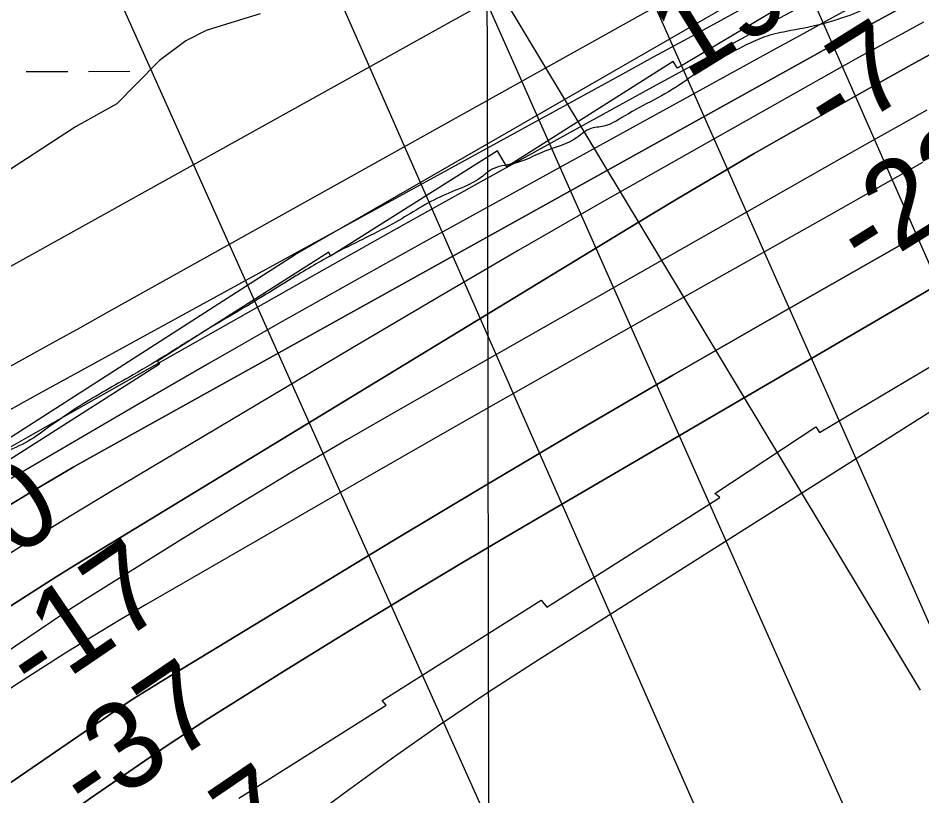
# Model space of a CAD drawing. Extents: x 3324104 to 3361979, y 612876 to 638273.
# Drawn here: x 3354171 to 3354870, y 621658 to 622260 of the extents above; entities that cross this region are included whole.
import ezdxf

# ---------------------------------------------------------------- set-up
doc = ezdxf.new("R2010")
doc.units = 0
for name, color, linetype in [('V-GRID-MAJR', 7, 'Continuous'), ('V-RIVR-EDGE', 7, 'Continuous'), ('V-RIVR-RANG', 7, 'Continuous'), ('V-RRAP-FSHR', 7, 'Continuous'), ('V-RRAP-RVMT', 7, 'Continuous'), ('V-TOPO-DPTH', 7, 'Continuous'), ('V-TOPO-MAJR', 7, 'Continuous'), ('V-TOPO-MINR', 7, 'Continuous'), ('V-TOPO-WATR', 7, 'Continuous'), ('V-UTIL-LINE', 7, 'Continuous'), ('V-WETL-SWMP', 7, 'Continuous')]:
    doc.layers.add(name, color=color, linetype=linetype)

msp = doc.modelspace()

# ---------------------------------------------------------------- linework, layer by layer
at = {"layer": 'V-GRID-MAJR'}
msp.add_spline([(3354542.62, 618302.88), (3354530.28, 624362.21), (3354517.94, 630423.47), (3354505.59, 636484.76), (3354505.59, 636486.67)], degree=3, dxfattribs=at)
at = {"layer": 'V-RIVR-EDGE'}
msp.add_spline([(3356051.95, 622889.63), (3356029.15, 622881.43), (3356012.46, 622875.66), (3355994.6, 622867.17), (3355977.52, 622859.07), (3355958.5, 622850.97), (3355948.4, 622843.24), (3355934.03, 622834.75), (3355904.12, 622817.76), (3355878.1, 622802.31), (3355856.74, 622790.34), (3355829.95, 622776.44), (3355805.11, 622765.65), (3355764.72, 622744.81), (3355744.14, 622733.61), (3355694.06, 622710.85), (3355668.43, 622698.12), (3355641.64, 622685), (3355605.15, 622669.19), (3355569.44, 622657.26), (3355539.17, 622646.47), (3355510.83, 622636.85), (3355482.11, 622628.39), (3355461.93, 622623.01), (3355442.52, 622614.14), (3355422.73, 622607.21), (3355409.53, 622603.36), (3355388.97, 622597.59), (3355371.88, 622589.49), (3355348.98, 622581.02), (3355297.71, 622547.02), (3355260.04, 622525.78), (3355211.1, 622494.49), (3355190.13, 622484.46), (3355184.7, 622482.92), (3355179.26, 622477.89), (3355174.21, 622475.58), (3355160.62, 622470.96), (3355143.54, 622463.63), (3355133.06, 622457.07), (3355125.67, 622450.49), (3355113.25, 622443.93), (3355096.93, 622433.11), (3355081.02, 622426.95), (3355064.32, 622419.23), (3355056.95, 622418.86), (3355048.8, 622414.62), (3355041.8, 622406.88), (3355036.76, 622406.5), (3355031.32, 622405.74), (3355027.05, 622404.2), (3355017.34, 622396.08), (3355010.74, 622394.93), (3355001.42, 622388.36), (3354988.6, 622379.09), (3354972.29, 622369.43), (3354947.44, 622356.31), (3354937.73, 622351.68), (3354926.08, 622343.56), (3354903.15, 622326.56), (3354891.11, 622318.06), (3354883.33, 622307.22), (3354879.44, 622304.12), (3354875.17, 622302.58), (3354867.8, 622299.11), (3354853.03, 622288.29), (3354842.54, 622279.01), (3354826.61, 622267.41), (3354807.2, 622259.71), (3354793.23, 622255.47), (3354765.68, 622249.73), (3354748.61, 622245.5), (3354734.63, 622239.33), (3354712.11, 622227.37), (3354697.74, 622218.87), (3354685.31, 622209.98), (3354640.65, 622184.5), (3354622.01, 622176.01), (3354616.19, 622175.25), (3354603.38, 622167.52), (3354578.92, 622157.11), (3354554.46, 622147.48), (3354537.39, 622142.87), (3354530.78, 622137.84), (3354500.11, 622122.79), (3354463.61, 622102.33), (3354417.79, 622078.79), (3354386.33, 622060.64), (3354340.11, 622032.44), (3354321.08, 622021.25), (3354284.96, 621998.84), (3354257, 621982.24), (3354217, 621958.68), (3354194.08, 621942.84), (3354176.99, 621931.63), (3354157.57, 621921.98), (3354141.64, 621910.39), (3354135.42, 621904.2), (3354130.36, 621897.62), (3354120.65, 621891.05), (3354103.96, 621882.95), (3354075.58, 621856.65), (3354044.89, 621835.39), (3354013.04, 621812.21), (3353971.47, 621781.67), (3353947.77, 621763.5), (3353941.17, 621763.52), (3353935.35, 621762.76), (3353929.53, 621760.06), (3353924.87, 621756.58), (3353920.59, 621751.55), (3353917.08, 621742.64), (3353910.48, 621741.49), (3353904.66, 621738.4), (3353893.78, 621731.06), (3353879.8, 621721.4), (3353866.19, 621708.64), (3353854.92, 621697.42), (3353843.26, 621687.75), (3353839.77, 621688.54), (3353831.23, 621686.23), (3353823.08, 621681.21), (3353818.03, 621677.34), (3353800.94, 621666.14), (3353790.85, 621663.06), (3353781.91, 621654.94), (3353777.63, 621651.85), (3353776.07, 621648.75), (3353775.67, 621643.71), (3353772.18, 621641), (3353755.87, 621632.13), (3353735.68, 621622.09), (3353718.58, 621608.17), (3353704.21, 621600.45), (3353694.12, 621596.6), (3353683.64, 621592.36), (3353671.21, 621584.25), (3353642.07, 621562.99), (3353598.95, 621534.01), (3353578.37, 621522.43), (3353556.23, 621507.75), (3353547.68, 621501.95), (3353525.93, 621489.21), (3353513.12, 621481.09), (3353497.18, 621468.34), (3353476.98, 621450.94), (3353453.28, 621436.65), (3353435.8, 621424.67), (3353404.72, 621401.09), (3353378.3, 621380.21), (3353361.59, 621368.62), (3353339.46, 621355.1), (3353319.65, 621342.35), (3353299.45, 621329.99), (3353283.54, 621324.6), (3353273.05, 621317.65), (3353254.77, 621295.98), (3353236.88, 621275.47), (3353219.39, 621258.83), (3353195.69, 621241.44), (3353168.49, 621221.34), (3353137.81, 621201.64), (3353112.17, 621185.03), (3353065.55, 621151.79), (3353022.05, 621122.82), (3352993.29, 621100.39), (3352956, 621073.34), (3352907.05, 621037.78), (3352853.8, 620991.77), (3352787.76, 620942.29), (3352749.68, 620913.3), (3352736.85, 620900.92), (3352733.34, 620892.79), (3352728.67, 620886.59), (3352718.96, 620881.19), (3352691.78, 620864.58), (3352660.31, 620841.78), (3352640.5, 620828.25), (3352623.39, 620811.23), (3352605.12, 620792.27), (3352593.46, 620783), (3352582.59, 620778.76), (3352566.29, 620771.43), (3352548.04, 620764.49), (3352522.41, 620750.98), (3352494.45, 620735.54), (3352482.41, 620727.04), (3352479.3, 620723.17), (3352476.96, 620717.36), (3352470.74, 620711.94), (3352455.99, 620707.33), (3352443.18, 620700.38), (3352419.1, 620685.7), (3352392.3, 620669.09), (3352362.78, 620650.94), (3352339.08, 620634.32), (3352315.38, 620615.38), (3352284.68, 620590.63), (3352258.65, 620571.31), (3352228.74, 620550.05), (3352193.39, 620527.65), (3352156.88, 620504.86), (3352131.63, 620487.47), (3352093.95, 620462.36), (3352049.28, 620432.99), (3351990.23, 620391.26), (3351936.63, 620357.26), (3351851.55, 620293.87), (3351833.29, 620281.51), (3351816.98, 620273.79), (3351794.06, 620257.95), (3351767.65, 620240.95), (3351719.86, 620206.17), (3351680.63, 620177.57), (3351657.32, 620160.56), (3351637.11, 620145.87), (3351623.13, 620135.44), (3351603.32, 620124.24), (3351588.57, 620120.01), (3351567.22, 620109.59), (3351552.08, 620103.43), (3351538.1, 620096.48), (3351523.73, 620086.43), (3351510.91, 620076.38), (3351503.52, 620069.81), (3351495.35, 620057.42), (3351486, 620042.32), (3351479.39, 620032.64), (3351469.67, 620022.58), (3351448.3, 620006.34), (3351431.59, 619994.75), (3351404.78, 619973.88), (3351377.97, 619951.84), (3351358.93, 619936.37), (3351332.12, 619915.5), (3351306.08, 619892.29), (3351274.58, 619858.25), (3351238.83, 619826.92), (3351215.12, 619805.65), (3351171.59, 619767.75), (3351145.54, 619739.51), (3351124.55, 619722.11), (3351105.9, 619707.81), (3351089.59, 619696.99), (3351079.49, 619691.2), (3351074.04, 619683.45), (3351058.1, 619666.43), (3351043.34, 619655.22), (3351015.36, 619633.96), (3350999.05, 619623.14), (3350992.05, 619617.34), (3350979.23, 619606.13), (3350966.01, 619594.53), (3350951.25, 619582.15), (3350935.7, 619567.84), (3350923.26, 619555.08), (3350910.05, 619544.25), (3350888.29, 619528.02), (3350846.74, 619504.08), (3350821.49, 619490.18), (3350811.39, 619483.61), (3350805.96, 619480.52), (3350800.9, 619473.16), (3350797.41, 619473.17), (3350793.92, 619474.35), (3350788.88, 619473.58), (3350786.93, 619472.04), (3350785.37, 619467.39), (3350785.36, 619462.73), (3350779.53, 619456.15), (3350765.93, 619445.72), (3350746.11, 619428.7), (3350722.4, 619408.98), (3350716.19, 619407.06), (3350713.08, 619403.96), (3350711.13, 619396.99), (3350708.79, 619391.57), (3350704.52, 619391.58), (3350693.26, 619385.79), (3350686.65, 619379.6), (3350679.64, 619368.37), (3350661.38, 619354.45), (3350648.56, 619344.4), (3350645.46, 619344.8), (3350638.47, 619339.39), (3350623.32, 619330.5), (3350616.33, 619326.26), (3350602.35, 619317.37), (3350598.83, 619308.85), (3350582.91, 619299.19), (3350553.77, 619276), (3350526.18, 619255.51), (3350493.55, 619231.94), (3350474.9, 619219.57), (3350474.5, 619213.76), (3350470.22, 619207.17), (3350458.96, 619202.55), (3350446.14, 619194.05), (3350441.09, 619189.79), (3350438.76, 619186.31), (3350434.48, 619180.89), (3350414.67, 619167.76), (3350401.46, 619159.26), (3350384.75, 619146.89), (3350369.6, 619133.74), (3350356.39, 619125.24), (3350350.95, 619119.05), (3350347.43, 619109.36), (3350338.1, 619097.75), (3350324.88, 619083.82), (3350308.55, 619069.9), (3350300.39, 619062.56), (3350296.13, 619062.57), (3350291.47, 619062.19), (3350274.77, 619050.6), (3350258.45, 619037.45), (3350251.84, 619032.81), (3350244.08, 619029.34), (3350233.61, 619028.21), (3350227.39, 619024.34), (3350220.39, 619016.99), (3350213, 619007.32), (3350202.12, 618996.87), (3350193.57, 618989.52), (3350179.6, 618985.29), (3350173.77, 618980.65), (3350164.84, 618977.96), (3350162.12, 618975.25), (3350159.39, 618971.38), (3350154.33, 618963.64), (3350145.78, 618953.19), (3350125.96, 618938.11), (3350102.66, 618923.05), (3350094.5, 618918.41), (3350086.34, 618913), (3350075.07, 618901.01), (3350064.19, 618892.12), (3350039.32, 618873.57), (3350021.84, 618861.59), (3350002.03, 618848.84), (3349991.94, 618844.21), (3349964.36, 618826.44), (3349938.72, 618807.11), (3349915.41, 618792.82), (3349892.5, 618778.92), (3349868.02, 618761.91), (3349852.49, 618753.03), (3349842.79, 618749.95), (3349830.35, 618739.13), (3349804.32, 618720.19), (3349777.9, 618697.76), (3349751.86, 618677.66), (3349729.72, 618661.43), (3349703.69, 618642.88), (3349678.84, 618629.75), (3349648.93, 618611.99), (3349624.46, 618594.99), (3349592.61, 618575.67), (3349570.48, 618564.87), (3349549.5, 618548.63), (3349505.21, 618518.11), (3349479.19, 618499.94), (3349471.42, 618494.53), (3349458.99, 618487.59), (3349438.4, 618472.12), (3349412.37, 618452.41), (3349379.73, 618429.61), (3349350.21, 618410.29), (3349303.2, 618374.73), (3349277.56, 618357.73), (3349263.97, 618347.29), (3349241.43, 618330.68), (3349226.67, 618319.85), (3349207.25, 618306.33), (3349193.17, 618293.54)], degree=3, dxfattribs=at)
at = {"layer": 'V-RIVR-RANG'}
msp.add_line((3354405.13, 622511.41), (3354869.13, 621740.23), dxfattribs=at)
at = {"layer": 'V-RRAP-FSHR'}
msp.add_lwpolyline([(3353211.76, 621284.79), (3354078.79, 621880.27), (3354385.88, 622077.34), (3354728.27, 622274.75), (3355278, 622569.49)], dxfattribs=at)
at = {"layer": 'V-RRAP-RVMT'}
for p, q in [((3354756.89, 622266.36), (3354681.44, 622221.28)), ((3354678.17, 622226.64), (3354549.53, 622145.06)), ((3354681.44, 622221.28), (3354678.17, 622226.64)), ((3354542.13, 622157.35), (3354413.04, 622075.9)), ((3354549.53, 622145.06), (3354542.13, 622157.35)), ((3354411.89, 622078.93), (3354279.26, 621994.82)), ((3354413.04, 622075.9), (3354411.89, 622078.93)), ((3354791.24, 621939.49), (3354900.92, 622004.91)), ((3354279.26, 621994.82), (3354280.77, 621992.32)), ((3354280.77, 621992.32), (3354052.63, 621846.84)), ((3354710.25, 621892.46), (3354788.5, 621944.06)), ((3354788.5, 621944.06), (3354791.24, 621939.49)), ((3354714.16, 621889.31), (3354710.25, 621892.46)), ((3354580.26, 621804.39), (3354714.16, 621889.31)), ((3354453.14, 621732.22), (3354576.1, 621809.95)), ((3354576.1, 621809.95), (3354580.26, 621804.39)), ((3354456.23, 621728.65), (3354453.14, 621732.22)), ((3354342.29, 621656.79), (3354456.23, 621728.65))]:
    msp.add_line(p, q, dxfattribs=at)
at = {"layer": 'V-TOPO-DPTH'}
for points in [[(3355320.3, 622563.61), (3354850.48, 622309.01), (3354820.61, 622292.81), (3354790.74, 622276.59), (3354760.88, 622260.36), (3354731.03, 622244.11), (3354662.2, 622206.62), (3354598.02, 622171.46), (3354533.96, 622136.1), (3354470.07, 622100.43), (3354406.29, 622064.56), (3354179.12, 621936.06), (3354160.95, 621925.62), (3354142.87, 621915), (3354124.95, 621904.12), (3354107.13, 621893.08), (3354004.93, 621828.76), (3353936.34, 621785.05), (3353868.06, 621740.85), (3353800.28, 621695.89)], [(3353707.63, 621578.6), (3354161.88, 621881.5), (3354164.42, 621883.15), (3354166.99, 621884.74), (3354184.37, 621895.24), (3354194.38, 621901.21), (3354204.44, 621907.12), (3354214.56, 621912.91), (3354224.73, 621918.63), (3354783.66, 622229.28), (3354796.78, 622236.56), (3354809.92, 622243.81), (3354823.08, 622251.02), (3354836.25, 622258.22), (3354942.17, 622315.88)], [(3353707.63, 621578.6), (3354161.88, 621881.5), (3354164.42, 621883.15), (3354166.99, 621884.74), (3354184.37, 621895.24), (3354194.38, 621901.21), (3354204.44, 621907.12), (3354214.56, 621912.91), (3354224.73, 621918.63), (3354783.66, 622229.28), (3354796.78, 622236.56), (3354809.92, 622243.81), (3354823.08, 622251.02), (3354836.25, 622258.22), (3354942.17, 622315.88)], [(3353803.01, 621568.04), (3353882.11, 621620.39), (3353961.41, 621672.42), (3354040.85, 621724.25), (3354168.82, 621807.38), (3354184.42, 621817.42), (3354200.08, 621827.36), (3354215.83, 621837.16), (3354231.63, 621846.87), (3354650.52, 622101.65), (3354680.51, 622119.72), (3354710.59, 622137.62), (3354740.82, 622155.27), (3354771.15, 622172.75), (3354801.61, 622190.02), (3354832.12, 622207.18), (3354862.73, 622224.17), (3354893.41, 622241.04)], [(3354893.41, 622241.04), (3354862.73, 622224.17), (3354832.12, 622207.18), (3354801.61, 622190.02), (3354771.15, 622172.75), (3354740.82, 622155.27), (3354710.59, 622137.62), (3354680.51, 622119.72), (3354650.52, 622101.65), (3354231.63, 621846.87), (3354215.83, 621837.16), (3354200.08, 621827.36), (3354184.42, 621817.42), (3354168.82, 621807.38), (3354040.85, 621724.25), (3353961.41, 621672.42), (3353882.11, 621620.39), (3353803.01, 621568.04)], [(3354870.89, 622148.37), (3354834.57, 622127.8), (3354798.23, 622107.27), (3354651.6, 622024.66), (3354580.97, 621984.71), (3354510.42, 621944.61), (3354440.01, 621904.27), (3354369.68, 621863.78), (3354270.43, 621806.41), (3354249.88, 621794.35), (3354229.44, 621782.11), (3354209.17, 621769.59), (3354189.01, 621756.89), (3354169.01, 621743.93), (3354149.12, 621730.81), (3354129.4, 621717.44), (3354109.79, 621703.92), (3353576.52, 621331.22)], [(3354870.89, 622148.37), (3354834.57, 622127.8), (3354798.23, 622107.27), (3354651.6, 622024.66), (3354580.97, 621984.71), (3354510.42, 621944.61), (3354440.01, 621904.27), (3354369.68, 621863.78), (3354270.43, 621806.41), (3354249.88, 621794.35), (3354229.44, 621782.11), (3354209.17, 621769.59), (3354189.01, 621756.89), (3354169.01, 621743.93), (3354149.12, 621730.81), (3354129.4, 621717.44), (3354109.79, 621703.92), (3353576.52, 621331.22)], [(3353773.92, 621398.37), (3353829.36, 621437.48), (3353885.03, 621476.24), (3353940.87, 621514.77), (3354240.5, 621720.16), (3354251.09, 621727.29), (3354261.75, 621734.3), (3354272.54, 621741.13), (3354283.39, 621747.83), (3354461.39, 621855.71), (3354533.25, 621898.87), (3354605.34, 621941.63), (3354677.78, 621983.8), (3354750.44, 622025.58), (3354869.67, 622093.49), (3354882.89, 622101.03)], [(3353773.92, 621398.37), (3353829.36, 621437.48), (3353885.03, 621476.24), (3353940.87, 621514.77), (3354240.5, 621720.16), (3354251.09, 621727.29), (3354261.75, 621734.3), (3354272.54, 621741.13), (3354283.39, 621747.83), (3354461.39, 621855.71), (3354533.25, 621898.87), (3354605.34, 621941.63), (3354677.78, 621983.8), (3354750.44, 622025.58), (3354869.67, 622093.49), (3354882.89, 622101.03)], [(3354892.23, 622059.54), (3354561.97, 621866.56), (3354515.58, 621839.19), (3354469.36, 621811.55), (3354423.37, 621783.52), (3354377.54, 621755.22), (3354347.04, 621736.2), (3354316.75, 621716.95), (3354286.7, 621697.35), (3354257, 621677.22), (3354227.54, 621656.75), (3354198.31, 621635.91), (3354169.18, 621614.95), (3354140.18, 621593.81), (3354111.27, 621572.54), (3353703.34, 621270.44)], [(3353703.34, 621270.44), (3354111.27, 621572.54), (3354140.18, 621593.81), (3354169.18, 621614.95), (3354198.31, 621635.91), (3354227.54, 621656.75), (3354257, 621677.22), (3354286.7, 621697.35), (3354316.75, 621716.95), (3354347.04, 621736.2), (3354377.54, 621755.22), (3354423.37, 621783.52), (3354469.36, 621811.55), (3354515.58, 621839.19), (3354561.97, 621866.56), (3354892.23, 622059.54)]]:
    msp.add_lwpolyline(points, dxfattribs=at)
at = {"layer": 'V-TOPO-MAJR'}
for points in [[(3355399.09, 622731.95), (3354773.79, 622403.37), (3354750.89, 622391.29), (3354728.01, 622379.16), (3354705.17, 622366.95), (3354682.36, 622354.7), (3354659.6, 622342.36), (3354636.86, 622329.97), (3354614.18, 622317.49), (3354591.52, 622304.95), (3354130.49, 622048.71), (3354102.32, 622032.73), (3354074.34, 622016.42), (3354046.66, 621999.63), (3354019.16, 621982.51), (3353988.26, 621962.9), (3353945.67, 621935.42), (3353903.35, 621907.52), (3353861.45, 621879.01), (3353819.82, 621850.09)], [(3354915.12, 621979.71), (3354573.65, 621763.5), (3354535.33, 621738.62), (3354497.41, 621713.16), (3354460.07, 621686.86), (3354423.12, 621659.98), (3354405.19, 621646.61), (3354377.53, 621625.96), (3354349.89, 621605.26), (3354322.3, 621584.51), (3354294.74, 621563.73), (3354222.87, 621509.4), (3354159.21, 621461.65), (3354095.32, 621414.23), (3354031.08, 621367.28), (3353966.61, 621320.66), (3353764.05, 621175.32)]]:
    msp.add_lwpolyline(points, dxfattribs=at)
at = {"layer": 'V-TOPO-MINR'}
for points in [[(3355320.3, 622563.61), (3354850.48, 622309.01), (3354820.61, 622292.81), (3354790.74, 622276.59), (3354760.88, 622260.36), (3354731.03, 622244.11), (3354662.2, 622206.62), (3354598.02, 622171.46), (3354533.96, 622136.1), (3354470.07, 622100.43), (3354406.29, 622064.56), (3354179.12, 621936.06), (3354160.95, 621925.62), (3354142.87, 621915), (3354124.95, 621904.12), (3354107.13, 621893.08), (3354004.93, 621828.76), (3353936.34, 621785.05), (3353868.06, 621740.85), (3353800.28, 621695.89)], [(3355046.39, 622438.81), (3354791.37, 622299.63), (3354786.02, 622296.72), (3354780.67, 622293.81), (3354775.31, 622290.9), (3354769.95, 622288.01), (3354733.36, 622268.25), (3354709.72, 622255.46), (3354686.09, 622242.63), (3354662.49, 622229.76), (3354638.9, 622216.86), (3354187.59, 621969.44), (3354157.99, 621952.93), (3354128.56, 621936.13), (3354099.38, 621918.9), (3354070.37, 621901.39), (3354055.79, 621892.44), (3354019.75, 621870.02), (3353983.9, 621847.3), (3353948.33, 621824.14), (3353912.95, 621800.7), (3353456.83, 621494.35)], [(3355085.85, 622415.02), (3354843.25, 622283.25), (3354821.86, 622271.61), (3354800.48, 622259.94), (3354779.12, 622248.24), (3354757.77, 622236.52), (3354484.53, 622086.18), (3354429.17, 622055.44), (3354373.96, 622024.42), (3354319, 621992.97), (3354264.2, 621961.23), (3354172.2, 621907.48), (3354163.55, 621902.35), (3354154.95, 621897.14), (3354146.43, 621891.82), (3354137.95, 621886.41), (3353891.14, 621726.73), (3353821.21, 621681.04)], [(3354873.55, 622385.51), (3354782.39, 622334.72), (3354772.45, 622329.18), (3354762.51, 622323.64), (3354752.57, 622318.1), (3354742.64, 622312.55), (3354240.96, 622032.59), (3354219.46, 622020.62), (3354197.94, 622008.68), (3354176.39, 621996.78), (3354154.83, 621984.91)], [(3354871.77, 622257.04), (3354829.53, 622234.06), (3354824.27, 622231.18), (3354819.01, 622228.28), (3354813.77, 622225.36), (3354808.53, 622222.43), (3354688.36, 622154.72), (3354623.18, 622117.69), (3354558.18, 622080.35), (3354493.46, 622042.53), (3354428.92, 622004.4), (3354242.97, 621893.63), (3354212.21, 621875.11), (3354181.56, 621856.39), (3354151.09, 621837.4), (3354120.74, 621818.21), (3354112.76, 621813.11), (3354078.55, 621791.17), (3354044.39, 621769.15), (3354010.32, 621746.99), (3353976.3, 621724.76), (3353607.3, 621482.6)], [(3354893.41, 622241.04), (3354862.73, 622224.17), (3354832.12, 622207.18), (3354801.61, 622190.02), (3354771.15, 622172.75), (3354740.82, 622155.27), (3354710.59, 622137.62), (3354680.51, 622119.72), (3354650.52, 622101.65), (3354231.63, 621846.87), (3354215.83, 621837.16), (3354200.08, 621827.36), (3354184.42, 621817.42), (3354168.82, 621807.38), (3354040.85, 621724.25), (3353961.41, 621672.42), (3353882.11, 621620.39), (3353803.01, 621568.04)], [(3354874.32, 622189), (3354852.28, 622176.59), (3354830.27, 622164.14), (3354808.27, 622151.67), (3354468.76, 621958.67), (3354425.84, 621933.92), (3354383.13, 621908.82), (3354340.74, 621883.21), (3354298.55, 621857.24), (3354223, 621810.1), (3354218.76, 621807.42), (3354214.53, 621804.71), (3354210.33, 621801.95), (3354206.15, 621799.15), (3353788.86, 621517.01)], [(3354870.89, 622148.37), (3354834.57, 622127.8), (3354798.23, 622107.27), (3354651.6, 622024.66), (3354580.97, 621984.71), (3354510.42, 621944.61), (3354440.01, 621904.27), (3354369.68, 621863.78), (3354270.43, 621806.41), (3354249.88, 621794.35), (3354229.44, 621782.11), (3354209.17, 621769.59), (3354189.01, 621756.89), (3354169.01, 621743.93), (3354149.12, 621730.81), (3354129.4, 621717.44), (3354109.79, 621703.92), (3353576.52, 621331.22)], [(3354882.89, 622101.03), (3354869.67, 622093.49), (3354750.44, 622025.58), (3354677.78, 621983.8), (3354605.34, 621941.63), (3354533.25, 621898.87), (3354461.39, 621855.71), (3354283.39, 621747.83), (3354272.54, 621741.13), (3354261.75, 621734.3), (3354251.09, 621727.29), (3354240.5, 621720.16), (3353940.87, 621514.77), (3353885.03, 621476.24), (3353829.36, 621437.48), (3353773.92, 621398.37)], [(3354892.23, 622059.54), (3354561.97, 621866.56), (3354515.58, 621839.19), (3354469.36, 621811.55), (3354423.37, 621783.52), (3354377.54, 621755.22), (3354347.04, 621736.2), (3354316.75, 621716.95), (3354286.7, 621697.35), (3354257, 621677.22), (3354227.54, 621656.75), (3354198.31, 621635.91), (3354169.18, 621614.95), (3354140.18, 621593.81), (3354111.27, 621572.54), (3353703.34, 621270.44)]]:
    msp.add_lwpolyline(points, dxfattribs=at)
at = {"layer": 'V-TOPO-WATR'}
msp.add_lwpolyline([(3354942.17, 622315.88), (3354836.25, 622258.22), (3354823.08, 622251.02), (3354809.92, 622243.81), (3354796.78, 622236.56), (3354783.66, 622229.28), (3354224.73, 621918.63), (3354214.56, 621912.91), (3354204.44, 621907.12), (3354194.38, 621901.21), (3354184.37, 621895.24), (3354166.99, 621884.74), (3354164.42, 621883.15), (3354161.88, 621881.5), (3353707.63, 621578.6)], dxfattribs=at)
at = {"layer": 'V-UTIL-LINE'}
for p, q in [((3354665.42, 622549.19), (3356175.84, 619111.69)), ((3354578.62, 622462.38), (3356071.67, 619094.33)), ((3354457.09, 622445.02), (3355984.87, 619007.52)), ((3354352.92, 622427.66), (3355880.7, 618955.44)), ((3354196.67, 622392.94), (3355776.53, 618868.63))]:
    msp.add_line(p, q, dxfattribs=at)
at = {"layer": 'V-WETL-SWMP'}
for p, q in [((3354177.83, 622218.8), (3354209.83, 622218.86)), ((3354225.83, 622218.89), (3354257.83, 622218.94))]:
    msp.add_line(p, q, dxfattribs=at)
msp.add_lwpolyline([(3354358.58, 622263.43), (3354332.64, 622255.47), (3354316.95, 622250.42), (3354301.29, 622242.62), (3354280.96, 622227.21), (3354262.73, 622209.08), (3354247.89, 622193.76), (3354215.93, 622176.1), (3354184.03, 622155.01), (3354155.52, 622136.72)], dxfattribs=at)

# ---------------------------------------------------------------- texts
at = {"layer": 'V-RIVR-RANG'}
for s, rotation, p in [('19.0', 31.70833, (3354688.68, 622211.89)), ('-7', 31.99, (3354800.96, 622163.42)), ('-22', 31.99, (3354826.44, 622061.43)), ('-0', 33.88833, (3354143.17, 621824.91)), ('-17', 34.17522, (3354185.23, 621732.3)), ('-37', 34.17522, (3354226.79, 621639.65)), ('-47', 34.17522, (3354285.82, 621558.85))]:
    msp.add_text(s, height=67, rotation=rotation, dxfattribs=at).set_placement(p)

doc.saveas('drawing.dxf')
